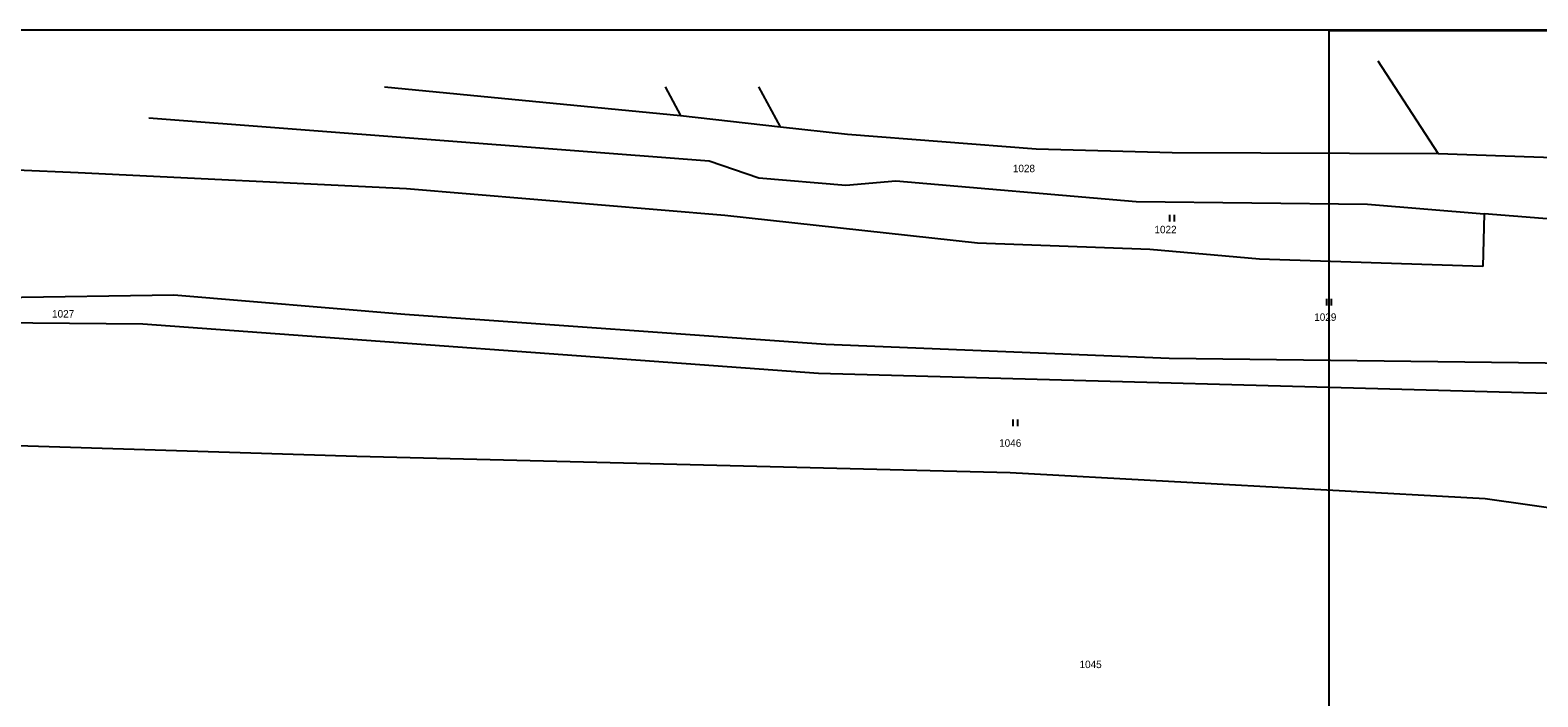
# Model space of a CAD drawing. Extents: x -604848 to -603227, y -1111879 to -1109838.
# Drawn here: x -604117.6 to -603773.6, y -1109989.7 to -1109837.8 of the extents above; entities that cross this region are included whole.
import ezdxf

# ---------------------------------------------------------------- set-up
doc = ezdxf.new("R2010")
doc.units = 0
for name, color, linetype in [('1', 7, 'Continuous'), ('14', 7, 'Continuous'), ('23', 7, 'Continuous'), ('7', 7, 'Continuous')]:
    doc.layers.add(name, color=color, linetype=linetype)

# ---------------------------------------------------------------- blocks, each defined once
blk = doc.blocks.new('Z3060')
at = {"layer": '23'}
for p, q in [((-0.5, 0), (-0.5, 1.5)), ((0.5, 1.5), (0.5, 0))]:
    blk.add_line(p, q, dxfattribs=at)

msp = doc.modelspace()

# ---------------------------------------------------------------- linework, layer by layer
at = {"layer": '1'}
for p, q in [((-603796.36, -1109865.91), (-603810.03, -1109844.87)), ((-604036.75, -1109850.75), (-603969.17, -1109857.23)), ((-603972.67, -1109850.75), (-603969.17, -1109857.23)), ((-603946.4, -1109859.8), (-603951.32, -1109850.75)), ((-603969.17, -1109857.23), (-603946.4, -1109859.8)), ((-604090.46, -1109857.75), (-603962.69, -1109867.62)), ((-603946.4, -1109859.8), (-603931.08, -1109861.53)), ((-603931.08, -1109861.53), (-603888.08, -1109864.87)), ((-603888.08, -1109864.87), (-603857.07, -1109865.68)), ((-603857.07, -1109865.68), (-603796.36, -1109865.91)), ((-603796.36, -1109865.91), (-603760.61, -1109867.14)), ((-604106.62, -1109870.34), (-604120.68, -1109869.74)), ((-604031.7, -1109874), (-604106.62, -1109870.34)), ((-603962.69, -1109867.62), (-603951.35, -1109871.49)), ((-603959.06, -1109880.06), (-604031.7, -1109874)), ((-603951.35, -1109871.49), (-603931.46, -1109873.13)), ((-603931.46, -1109873.13), (-603920.12, -1109872.14)), ((-603920.12, -1109872.14), (-603865.24, -1109876.83)), ((-603865.24, -1109876.83), (-603812.48, -1109877.48)), ((-603812.48, -1109877.48), (-603785.89, -1109879.64)), ((-603901.47, -1109886.31), (-603959.06, -1109880.06)), ((-603785.89, -1109879.64), (-603786.19, -1109891.68)), ((-603731.3, -1109884.06), (-603785.89, -1109879.64)), ((-603862.16, -1109887.77), (-603901.47, -1109886.31)), ((-603837.12, -1109889.96), (-603862.16, -1109887.77)), ((-603786.19, -1109891.68), (-603837.12, -1109889.96)), ((-604124.47, -1109898.69), (-604084.8, -1109898.15)), ((-604084.8, -1109898.15), (-604032.06, -1109902.53)), ((-604091.9, -1109904.81), (-604165.84, -1109904.11)), ((-603937.7, -1109916.02), (-604091.9, -1109904.81)), ((-604032.06, -1109902.53), (-603936.03, -1109909.36)), ((-603936.03, -1109909.36), (-603857.71, -1109912.52)), ((-603857.71, -1109912.52), (-603747.93, -1109913.92)), ((-603758.3, -1109920.98), (-603937.7, -1109916.02)), ((-604168.34, -1109930.89), (-604043.08, -1109934.91)), ((-604043.08, -1109934.91), (-603894.03, -1109938.58)), ((-603894.03, -1109938.58), (-603785.62, -1109944.51)), ((-603785.62, -1109944.51), (-603651.94, -1109963.71))]:
    msp.add_line(p, q, dxfattribs=at)
for points in [[(-603752.05, -1110677.81), (-603752.05, -1109837.81), (-604346.05, -1109837.81), (-604346.05, -1110677.81), (-603752.05, -1110677.81)], [(-603227.31, -1110677.93), (-603227.31, -1109837.93), (-603821.31, -1109837.93), (-603821.31, -1110677.93), (-603227.31, -1110677.93)]]:
    msp.add_lwpolyline(points, dxfattribs=at)
at = {"layer": '7'}
msp.add_open_spline([(-604096.53, -1110048.04), (-604098.4, -1110042.67), (-604100.25, -1110037.29), (-604102.12, -1110031.91), (-604104.84, -1110024.09), (-604111.2, -1110018.05), (-604115.63, -1110011.05), (-604120.2, -1110003.83), (-604124.7, -1109996.56), (-604129.28, -1109989.34), (-604134.06, -1109981.81), (-604139.33, -1109974.7), (-604145.1, -1109967.77), (-604151.28, -1109960.36), (-604158.5, -1109953.74), (-604166.92, -1109949.27), (-604174.06, -1109945.49), (-604181.2, -1109941.71), (-604188.34, -1109937.93)], degree=3, dxfattribs=at)

# ---------------------------------------------------------------- block references
at = {"layer": '23'}
for p in [(-603857.11, -1109881.41), (-603821.27, -1109900.54), (-603892.85, -1109928.04)]:
    msp.add_blockref('Z3060', p, dxfattribs=at)

# ---------------------------------------------------------------- texts
at = {"layer": '14'}
for s, p in [('1028', (-603893.39, -1109870.17)), ('1022', (-603861.09, -1109884.09)), ('1027', (-604112.57, -1109903.29)), ('1029', (-603824.64, -1109904.05)), ('1046', (-603896.52, -1109932.74)), ('1045', (-603878.18, -1109983.18))]:
    msp.add_text(s, height=1.7, dxfattribs=at).set_placement(p)

doc.saveas('drawing.dxf')
